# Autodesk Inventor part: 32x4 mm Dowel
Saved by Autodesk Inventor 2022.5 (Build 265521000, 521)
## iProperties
Created: 2025-01
Part Number: 32x4 mm Dowel
Material: Generic
Document SubType Name: Modeling
Designer: AdminForWorker
Density: 1 g/cm^3
Appearance: Default
Title: 32x4 mm Dowel v1
Author: AdminForWorker
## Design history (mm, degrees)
feature "Body1"
body "Solid1"
